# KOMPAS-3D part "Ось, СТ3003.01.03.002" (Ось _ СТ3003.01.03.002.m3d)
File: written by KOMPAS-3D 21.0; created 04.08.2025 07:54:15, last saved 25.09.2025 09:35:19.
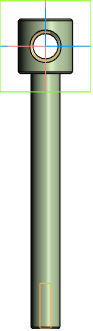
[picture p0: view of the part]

Document properties: Полное имя файла: C:\Users\1\Yandex.Disk\Документы\Новая папка\Стапель №2\Стапель _ СТ3003.00.00.000\Опора _ СТ3003.01.00.000\3D\Струбцина _ СТ3003.01.03.000\Ось _ СТ3003.01.03.002.m3d; Автор: 1

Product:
- Part/product: Ось  | designation СТ3003.01.03.002
    Материал: Круг$d30 ГОСТ 2590-2006;40Х ГОСТ 4543-2016$ (density 7850 kg/m3)
    Масса: 0.346686
    Форматы листов документа: A4

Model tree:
1. Эскиз:1
2. Элемент вращения:1
     Угол 1 = 360
3. Эскиз:2
4. Элемент выдавливания:1
     Расстояние 1 = 35
5. Условное изображение резьбы:1  (with: Элемент выдавливания:1)  (labels: M16; cil0_24705-2004 coarse)
     Длина резьбы = 30; Шаг резьбы = 2; Номинальный диаметр резьбы = 16
6. Подгонка:1  (with: Элемент выдавливания:1)
7. Фаска:1  (with: Элемент вращения:1)
     Угол = 45; Длина 1 = 1; Длина 2 = 1
8. Фаска:2  (with: Элемент выдавливания:1)
     Угол = 45; Длина 1 = 2; Длина 2 = 2
9. Эскиз:12  (with: Элемент вращения:1, Фаска:1)
10. ЛСК:8  (with: Плоскость XY, Плоскость ZX, Плоскость ZY, Ось X, Ось Y, Ось Z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)
     Ось X. Z = -1; Ось Y. X = 1; Ось Z. Y = -1; Координата Z = -155; Точка начала. Z = -155
11. Эскиз:13
12. Элемент вращения:4
     Угол 1 = 360
13. Смещенная плоскость:3  (with: Элемент вращения:1)
     Расстояние = 0.458734
14. Условное изображение резьбы:4  (with: Элемент вращения:4)  (labels: 6x1)
     Длина резьбы = 24.5413; Шаг резьбы = 1; Номинальный диаметр резьбы = 6
15. Подгонка:3
16. Отверстие М6x25-30/1x45°  (labels: Круг$d30 ГОСТ 2590-2006;40Х ГОСТ 4543-2016$)

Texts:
  KTE.LIST=LTWD36N5dmSErgwNQxupvb
  Edge1
  Edge2
  Центр круглого ребра
  СТ3003.01.03.002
